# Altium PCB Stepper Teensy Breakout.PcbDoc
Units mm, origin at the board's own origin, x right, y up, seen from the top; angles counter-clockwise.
Board outline 195.58 x 105.66 mm, 2 copper layers (Top Layer, Bottom Layer); 65 components, 54 nets, 291 pads, 5 vias.
Unrouted connection lines stored in the file: 1.
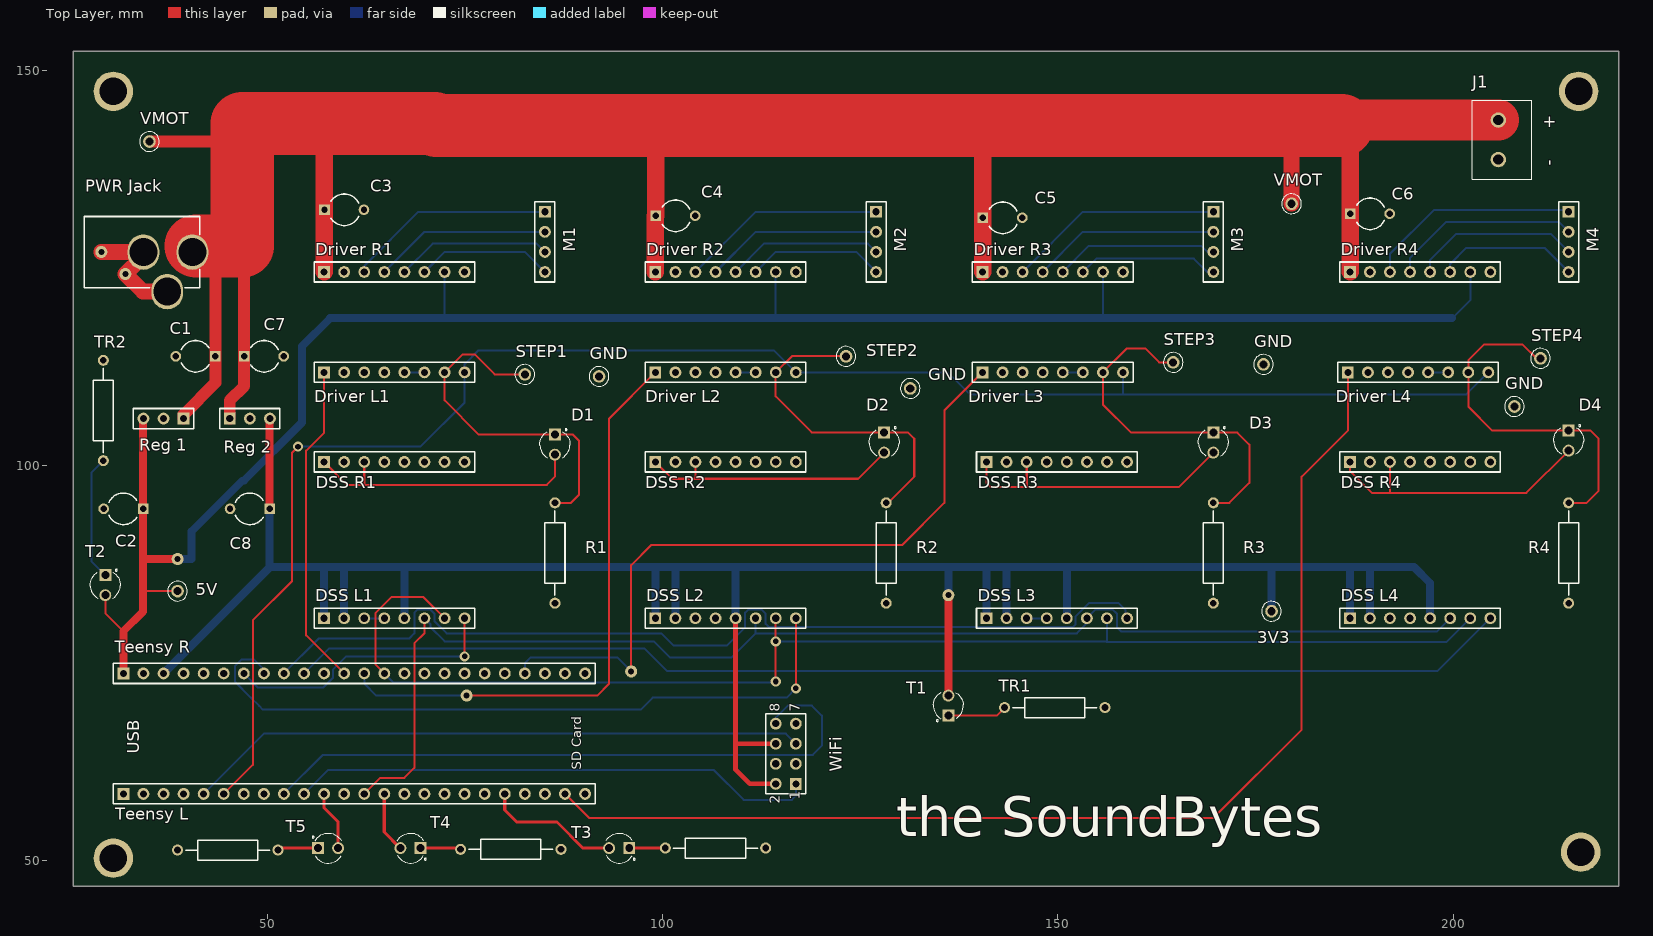
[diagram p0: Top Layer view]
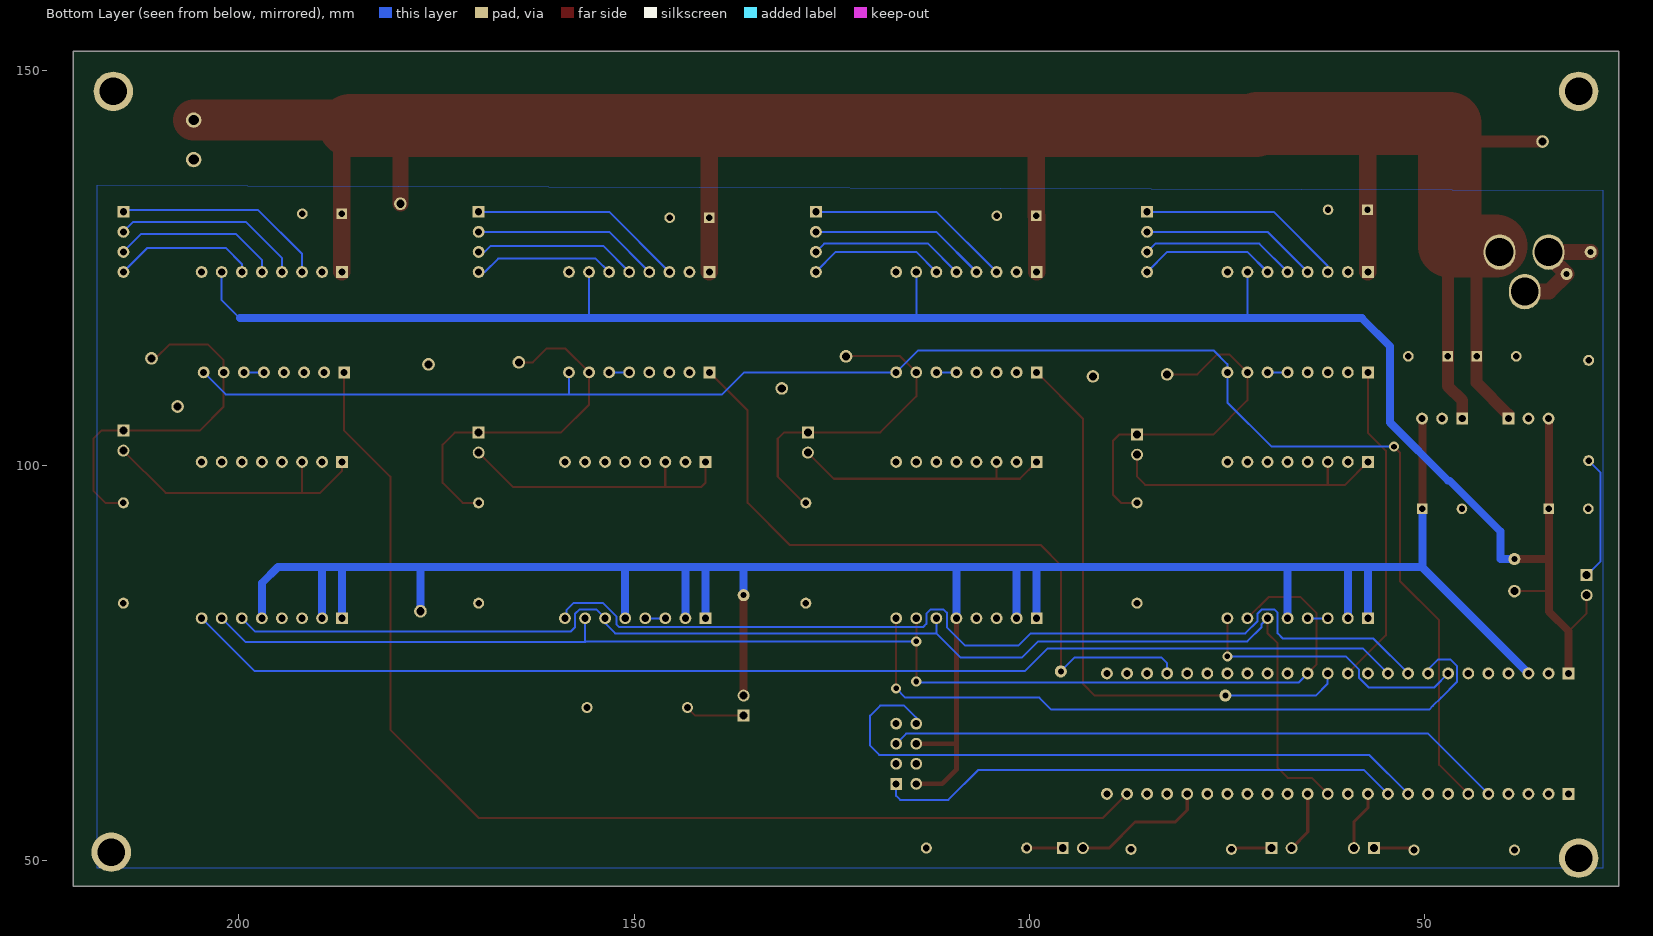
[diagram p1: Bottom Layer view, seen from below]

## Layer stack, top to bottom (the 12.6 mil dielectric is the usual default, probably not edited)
Top Solder: solder mask 0.0102, Solder Resist, Dk 3.5
Top Layer: signal copper 0.0356
Dielectric 1: dielectric 0.32, FR-4, Dk 4.8
Bottom Layer: signal copper 0.0356
Bottom Solder: solder mask 0.0102, Solder Resist, Dk 3.5

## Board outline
25.4,46.736 220.98,46.736 220.98,152.4 25.4,152.4

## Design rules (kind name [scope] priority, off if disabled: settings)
Clearance [All] p1: gap=0.254
PolygonConnect [All] p1: connectstyle=Relief reliefconductorwidth=0.254 reliefentries=4 polygonreliefangle="90 Angle" airgapwidth=0.254
RoutingVias [All] p1: holewidth=0.711 width=1.27 viastyle="Through Hole" minholewidth=0.711 minwidth=1.27 maxholewidth=0.711 maxwidth=1.27
SolderMaskExpansion [All] p1: expansion=0.102
Width Width_1 [All] p1: maxlimit=0.28 minlimit=0.28 preferedwidth=0.28 minimp=50.000000 maximp=50.000000 favimp=50.000000
Width [InNet('VMOT')] p2: maxlimit=8.2 minlimit=7.6 preferedwidth=8 minimp=50.000000 maximp=50.000000 favimp=50.000000
30 further rules are at their usual default settings.

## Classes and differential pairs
component class "Stepper Teensy Breakout": 3V3 5V C1 C2 C3 C4 C5 C6 C7 C8 D1 D2 D3 D4 "Driver L1" "Driver L2" "Driver L3" "Driver L4" "Driver R1" "Driver R2" "Driver R3" "Driver R4" "DSS L1" "DSS L2" "DSS L3" "DSS L4" "DSS R1" "DSS R2" "DSS R3" "DSS R4" GND J1 M1 M2 M3 M4 "PWR Jack" R1 R2 R3 R4 "Reg 1" "Reg 2" STEP1 STEP2 STEP3 STEP4 T1 T2 T3 T4 T5 "Teensy L" "Teensy R" TR1 TR2 VMOT WiFi ""

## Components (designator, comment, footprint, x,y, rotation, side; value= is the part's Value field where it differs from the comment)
3V3 "" TPCW51D250H460P 177.038,81.534 r0 top (schematic designator TP11)
5V "" TPCW51D250H460P 38.608,84.074 r90 top (schematic designator TP10)
C1 "Cap2" CAPR5-4X5 40.894,113.792 r180 top
C2 "Cap2" CAPR5-4X5 31.75,94.488 r180 top
C3 "" CAPR5-4X5 59.69,132.334 r0 top
C4 "Cap2" CAPR5-4X5 101.6,131.572 r0 top
C5 "Cap2" CAPR5-4X5 143.002,131.318 r0 top
C6 "Cap2" CAPR5-4X5 189.484,131.826 r0 top
C7 "Cap2" CAPR5-4X5 49.53,113.792 r0 top
C8 "Cap2" CAPR5-4X5 47.752,94.488 r180 top
D1 "LED2" LED_LTL-1CHYE_LTL-1CHYE(Primary) 86.36,102.616 r270 top
D2 "LED2" LED_LTL-1CHYE_LTL-1CHYE(Primary) 128.016,102.87 r270 top
D3 "LED2" LED_LTL-1CHYE_LTL-1CHYE(Primary) 169.672,102.87 r270 top
D4 "LED2" LED_LTL-1CHYE_LTL-1CHYE(Primary) 214.63,103.124 r270 top
"Driver L1" "Header 8" HDR1X8 57.15,111.76 r0 top locked
"Driver L2" "Header 8" HDR1X8 99.06,111.76 r0 top locked
"Driver L3" "Header 8" HDR1X8 140.462,111.76 r0 top locked
"Driver L4" "Header 8" HDR1X8 186.69,111.76 r0 top locked
"Driver R1" "Header 8" HDR1X8 57.15,124.46 r0 top locked
"Driver R2" "Header 8" HDR1X8 99.06,124.46 r0 top locked
"Driver R3" "Header 8" HDR1X8 140.462,124.46 r0 top locked
"Driver R4" "Header 8" HDR1X8 186.944,124.46 r0 top locked
"DSS L1" "Header 8" HDR1X8 57.15,80.645 r0 top locked
"DSS L2" "Header 8" HDR1X8 99.06,80.645 r0 top
"DSS L3" "Header 8" HDR1X8 140.97,80.645 r0 top locked
"DSS L4" "Header 8" HDR1X8 186.944,80.645 r0 top
"DSS R1" "Header 8" HDR1X8 57.15,100.42 r0 top locked
"DSS R2" "Header 8" HDR1X8 99.06,100.42 r0 top
"DSS R3" "Header 8" HDR1X8 140.97,100.42 r0 top
"DSS R4" "Header 8" HDR1X8 186.944,100.42 r0 top
GND "" TPCW51D250H460P 207.772,107.442 r0 top (schematic designator TP8)
GND "" TPCW51D250H460P 91.948,111.252 r0 top (schematic designator TP7)
GND "" TPCW51D250H460P 176.022,112.776 r0 top (schematic designator TP6)
GND "" TPCW51D250H460P 131.318,109.728 r0 top (schematic designator TP5)
J1 "" 691102710002 205.74,141.184 r270 top
M1 "Header 4" HDR1X4 85.09,132.08 r270 top (schematic designator "Motor 1")
M2 "Header 4" HDR1X4 127,132.08 r270 top (schematic designator "Motor 2")
M3 "Header 4" HDR1X4 169.672,132.08 r270 top (schematic designator "Motor 3")
M4 "Header 4" HDR1X4 214.63,132.08 r270 top (schematic designator "Motor 4")
"PWR Jack" "PWR2.5" KLD-0202 26.79,126.984 r0 top
R1 "Res Semi" AXIAL-0.5 86.36,88.9 r90 top
R2 "Res Semi" AXIAL-0.5 128.27,88.9 r90 top
R3 "Res Semi" AXIAL-0.5 169.672,88.9 r90 top
R4 "Res Semi" AXIAL-0.5 214.63,88.9 r90 top
"Reg 1" "Header 3" HDR1X3 39.37,105.918 r180 top (schematic designator "Sw Reg")
"Reg 2" "Header 2" HDR1X3 45.212,105.918 r0 top (schematic designator "Sw Reg1")
STEP1 "" TPCW51D250H460P 82.55,111.506 r0 top (schematic designator TP1)
STEP2 "" TPCW51D250H460P 123.19,113.792 r0 top (schematic designator TP2)
STEP3 "" TPCW51D250H460P 164.592,113.03 r0 top (schematic designator TP3)
STEP4 "" TPCW51D250H460P 211.074,113.538 r0 top (schematic designator TP4)
T1 "LTL-1CHYE" LED_LTL-1CHYE_LTL-1CHYE(Primary) 136.144,69.596 r90 top
T2 "LTL-1CHYE" LED_LTL-1CHYE_LTL-1CHYE(Primary) 29.464,84.836 r270 top
T3 "LTL-1CHYE" LED_LTL-1CHYE_LTL-1CHYE(Primary) 94.488,51.562 r180 top
T4 "LTL-1CHYE" LED_LTL-1CHYE_LTL-1CHYE(Primary) 68.072,51.562 r180 top
T5 "LTL-1CHYE" LED_LTL-1CHYE_LTL-1CHYE(Primary) 57.658,51.562 r0 top
"Teensy L" "Header 24" HDR1X24 31.75,58.42 r0 top locked
"Teensy R" "Header 24" HDR1X24 31.75,73.66 r0 top locked
TR1 "" AXIAL-0.5 149.606,69.342 r180 top
TR2 "" AXIAL-0.5 29.21,106.934 r270 top
TR3 "" AXIAL-0.5 106.68,51.562 r180 top
TR4 "" AXIAL-0.5 80.772,51.402 r180 top
TR5 "" AXIAL-0.5 44.958,51.308 r180 top
VMOT "" TPCW51D250H460P 179.578,133.096 r180 top (schematic designator TP12)
VMOT "" TPCW51D250H460P 35.052,140.97 r0 top (schematic designator TP9)
WiFi "Header 4X2" HDR2X4 116.84,59.69 r90 top (schematic designator ESP)

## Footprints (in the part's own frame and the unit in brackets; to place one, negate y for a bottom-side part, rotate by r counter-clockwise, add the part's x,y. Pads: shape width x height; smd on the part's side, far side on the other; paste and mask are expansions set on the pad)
691102710002 [mm]
  round 1.95 hole 1.3: 1(-2.5,0) 2(2.5,0)
  silkscreen extent -5,-3.3 5,4.2
AXIAL-0.5 [mm] "Axial Device, Thru-Hole; 2 Leads; 0.5 in Pin Spacing"
  round 1.4 hole 0.85: 1(-6.35,0) 2(6.35,0)
  silkscreen extent -5.33,-1.27 5.33,1.27
CAPR5-4X5 [mm] "Capacitor; 2 Leads"
  rect 1.35x1.35 hole 0.8: 1(-2.5,0)
  round 1.35 hole 0.8: 2(2.5,0)
  silkscreen extent -1.69,-2 1.82,2
HDR1X3 [mm] "Connector; Header; 3 Position"
  rect 1.5x1.5 hole 0.9: 1(0,0)
  round 1.5 hole 0.9: 2(2.54,0) 3(5.08,0)
  silkscreen extent -1.27,-1.27 6.35,1.27
HDR1X4 [mm] "Connector; Header; 4 Position"
  rect 1.5x1.5 hole 0.9: 1(0,0)
  round 1.5 hole 0.9: 2(2.54,0) 3(5.08,0) 4(7.62,0)
  silkscreen extent -1.27,-1.27 8.89,1.27
HDR1X8 [mm] "Connector; Header; 8 Position"
  rect 1.5x1.5 hole 0.9: 1(0,0)
  round 1.5 hole 0.9: 2(2.54,0) 3(5.08,0) 4(7.62,0) 5(10.16,0) 6(12.7,0) 7(15.24,0) 8(17.78,0)
  silkscreen extent -1.27,-1.27 19.05,1.27
HDR1X24 [mm] "Connector; Header; 24 Position"
  rect 1.5x1.5 hole 0.9: 1(0,0)
  round 1.5 hole 0.9: 2(2.54,0) 3(5.08,0) 4(7.62,0) 5(10.16,0) 6(12.7,0) 7(15.24,0) 8(17.78,0) 9(20.32,0) 10(22.86,0) 11(25.4,0) 12(27.94,0) 13(30.48,0) 14(33.02,0) 15(35.56,0) 16(38.1,0) 17(40.64,0) 18(43.18,0) 19(45.72,0) 20(48.26,0) 21(50.8,0) 22(53.34,0) 23(55.88,0) 24(58.42,0)
  silkscreen extent -1.27,-1.27 59.69,1.27
HDR2X4 [mm] "Connector; Header; 4x2 Position"
  rect 1.5x1.5 hole 0.9: 1(0,0)
  round 1.5 hole 0.9: 2(0,2.54) 3(2.54,0) 4(2.54,2.54) 5(5.08,0) 6(5.08,2.54) 7(7.62,0) 8(7.62,2.54)
  silkscreen extent -1.27,-1.27 8.89,3.81
KLD-0202 [mm] "DC Power Jack, 2.5mm, KLD Series, PCB Mount"
  oval 4x4.5 hole 3.5: 1(13.7,0) 2(7.5,0) 3(10.5,-5)
  round 1.5 hole 0.2: 1A(13.7,-1.25) 1B(13.7,1.25) 2A(7.5,-1) 2B(7.5,1) 3A(9.5,-5) 3B(11.5,-5)
  silkscreen extent 0,-4.5 14.6,4.5
LED_LTL-1CHYE_LTL-1CHYE(Primary) [mm]
  round 1.508 hole 1: A(1.27,0)
  rect 1.508x1.508 hole 1: C(-1.27,0)
  silkscreen extent -2.03,-1.9 1.66,1.9
TPCW51D250H460P [mm]
  round 1.6 hole 1.02: 1(0,0)
  silkscreen extent -1.25,-1.25 1.25,1.25

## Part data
3V3 5V GND GND GND GND STEP1 STEP2 STEP3 STEP4 VMOT VMOT: library part 5003, "Test Point; Orange; Thru-Hole; Snap-Fit; SilverPlate; 0.040 in. Dia.; 0.300 In."
C1 C2 C4 C5 C6 C7 C8: "Capacitor"
C3: library part Cap2, "Capacitor"
D1 D2 D3 D4: library part LTL-1CHYE, "Yellow 3.1 mm 45° Tinted Clear 40 mcd 2.1 V LED Through Hole"
"Driver L1" "Driver L2" "Driver L3" "Driver L4" "Driver R1" "Driver R2" "Driver R3" "Driver R4" "DSS L1" "DSS L2" "DSS L3" "DSS L4" "DSS R1" "DSS R2" "DSS R3" "DSS R4": "Header, 8-Pin"
J1: library part 691102710002, "102 Series 5mm Pitch Straight, PCB Terminal Block, Through Hole, 2 Way"
M1 M2 M3 M4: "Header, 4-Pin"
"PWR Jack": "Low Voltage Power Supply Connector"
R1 R2 R3 R4: "Semiconductor Resistor"
"Reg 1": "Header, 3-Pin"
"Reg 2": library part "Header 3", "Header, 3-Pin"
T1 T2 T3 T4 T5: "Yellow 3.1 mm 45° Tinted Clear 40 mcd 2.1 V LED Through Hole"
"Teensy L" "Teensy R": "Header, 24-Pin"
TR1 TR2 TR3 TR4 TR5: library part "Res Semi", "Semiconductor Resistor"
WiFi: "Header, 4-Pin, Dual row"

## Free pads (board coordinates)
  round 5 hole 3.5: 0(30.48,147.32) 6(215.9,147.32) 7(216.154,51.054) 8(30.48,50.292)
  round 1.524 hole 0.762: 2(28.956,127) 3(32.004,124.206) 5(38.608,88.138) 9(75.184,70.866) 10(96.012,73.914) 11(136.144,83.566)

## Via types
v1: diameter 1.27, hole 0.711, Top Layer to Bottom Layer, 5 vias

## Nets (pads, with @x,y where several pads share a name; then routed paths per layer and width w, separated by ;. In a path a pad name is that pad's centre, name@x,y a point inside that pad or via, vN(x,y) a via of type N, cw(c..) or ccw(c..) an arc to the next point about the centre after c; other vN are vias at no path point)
1A_A: "Driver R1.5" M1.3 | length 19.7
  Bottom Layer w0.254: 67.31,124.46 70.891,128.041 84.049,128.041 M1.3
1A_B: "Driver R2.5" M2.3 | length 19.7
  Bottom Layer w0.254: 109.22,124.46 112.801,128.041 125.959,128.041 M2.3
1A_C: "Driver R3.5" M3.3 | length 20.7
  Bottom Layer w0.254: 150.622,124.46 153.924,127.762 168.148,127.762 168.91,127 M3.3
1A_D: "Driver R4.5" M4.3 | length 21.4
  Bottom Layer w0.254: 197.104,124.46 197.104,125.984 200.406,129.286 212.344,129.286 M4.3
1B_A: "Driver R1.6" M1.4 | length 17.3
  Bottom Layer w0.254: 69.85,124.46 72.39,127 82.55,127 M1.4
1B_B: "Driver R2.6" M2.4 | length 17.3
  Bottom Layer w0.254: 111.76,124.46 114.3,127 124.46,127 M2.4
1B_C: "Driver R3.6" M3.4 | length 17.9
  Bottom Layer w0.254: 153.162,124.46 154.864,126.162 167.208,126.162 168.91,124.46 M3.4
1B_D: "Driver R4.6" M4.4 | length 18.1
  Bottom Layer w0.254: 199.644,124.46 199.644,125.476 201.676,127.508 211.582,127.508 M4.4
2A_A: "Driver R1.4" M1.2 | length 22.4
  Bottom Layer w0.254: 64.77,124.46 69.85,129.54 M1.2
2A_B: "Driver R2.4" M2.2 | length 22.4
  Bottom Layer w0.254: 106.68,124.46 111.76,129.54 M2.2
2A_C: "Driver R3.4" M3.2 | length 23.7
  Bottom Layer w0.254: 148.082,124.46 153.162,129.54 M3.2
2A_D: "Driver R4.4" M4.2 | length 24.3
  Bottom Layer w0.254: 194.564,124.46 194.564,126.238 199.136,130.81 213.36,130.81 M4.2
2B_A: "Driver R1.3" M1.1 | length 26.5
  Bottom Layer w0.254: 62.23,124.46 62.23,125.222 69.088,132.08 M1.1
2B_B: "Driver R2.3" M2.1 | length 26
  Bottom Layer w0.254: 104.14,124.46 111.76,132.08 M2.1
2B_C: "Driver R3.3" M3.1 | length 27.3
  Bottom Layer w0.254: 145.542,124.46 153.162,132.08 M3.1
2B_D: "Driver R4.3" M4.1 | length 27.3
  Bottom Layer w0.254: 192.024,124.46 192.024,126.746 197.612,132.334 214.376,132.334 M4.1
3V3: 3V3.1 "DSS L1.1" "DSS L1.2" "DSS L1.5" "DSS L2.1" "DSS L2.2" "DSS L2.5" "DSS L3.1" "DSS L3.2" "DSS L3.5" "DSS L4.1" "DSS L4.2" "DSS L4.5" "Reg 2.3" "Teensy R.3" C8.1 pad.11 T1.A WiFi.2 WiFi.6 | length 313.1
  Top Layer w0.6: 109.22,80.645 109.22,64.77 ; WiFi.2 110.998,59.69 109.22,61.468 109.22,64.77 ; WiFi.6 109.22,64.77
  Top Layer w1: C8.1 50.252,105.878 50.292,105.918 ; T1.A pad.11
  Bottom Layer w1: 36.83,73.66 50.252,87.082 50.252,87.122 ; C8.1 50.252,87.122 ; 57.15,80.645 57.15,87.122 ; 59.69,80.645 59.69,87.122 ; 67.31,80.645 67.31,87.122 ; 99.06,80.645 99.06,87.122 ; 101.6,80.645 101.6,87.122 ; 109.22,80.645 109.22,87.122 ; pad.11 136.144,87.122 ; 140.97,80.645 140.97,87.122 ; 143.51,80.645 143.51,87.122 ; 151.13,80.645 151.13,87.122 ; 3V3.1 177.038,87.122 ; 186.944,80.645 186.944,87.122 ; 189.484,80.645 189.484,87.122 ; 197.104,80.645 197.104,85.09 195.072,87.122 189.484,87.122 ; 50.252,87.122 57.15,87.122 ; 57.15,87.122 59.69,87.122 ; 59.69,87.122 67.31,87.122 ; 67.31,87.122 99.06,87.122 ; 99.06,87.122 101.6,87.122 ; 101.6,87.122 109.22,87.122 ; 109.22,87.122 136.144,87.122 ; 136.144,87.122 140.97,87.122 ; 140.97,87.122 143.51,87.122 ; 143.51,87.122 151.13,87.122 ; 151.13,87.122 177.038,87.122 ; 177.038,87.122 186.944,87.122 ; 186.944,87.122 189.484,87.122
5V: 5V.1 "Driver R1.7" "Driver R2.7" "Driver R3.7" "Driver R4.7" "Reg 1.3" "Teensy R.1" C2.1 pad.5 T2.A | length 253.5
  Top Layer w0.254: T2.A 29.464,81.28 31.75,78.994 ; 34.25,84.074 5V.1
  Top Layer w1: 31.75,73.66 31.75,78.994 34.25,81.494 34.25,84.074 34.25,88.138 ; 34.29,105.918 34.25,105.878 C2.1 34.25,88.138 ; pad.5 34.25,88.138
  Bottom Layer w0.254: 72.39,118.618 72.39,124.46 ; 114.3,118.618 114.3,124.46 ; 155.702,118.618 155.702,124.46 ; 199.898,118.618 202.184,120.904 202.184,124.46
  Bottom Layer w1: pad.5 40.393,88.138 40.393,91.65 46.787,98.044 46.99,98.044 54.356,105.41 54.356,115.062 57.912,118.618 72.39,118.618 114.3,118.618 155.702,118.618 199.898,118.618
24: "Teensy L.14" T4.A | length 7.7
  Top Layer w0.4: 64.77,58.42 64.77,53.594 T4.A
28: "Teensy L.20" T3.A | length 17.2
  Top Layer w0.4: 80.01,58.42 80.01,56.388 81.534,54.864 86.614,54.864 89.916,51.562 T3.A
CS1: "DSS L1.8" "Teensy R.7" | length 35.7
  Top Layer w0.254: v1(74.93,75.819) 74.93,80.645
  Bottom Layer w0.254: 46.99,73.66 48.768,71.882 57.023,71.882 58.293,73.152 58.293,74.168 59.944,75.819 v1(74.93,75.819)
CS2: "DSS L2.8" "Teensy R.8" | length 89.4
  Top Layer w0.254: v1(116.84,71.78) 116.84,80.645
  Bottom Layer w0.254: 49.53,73.66 49.53,74.168 48.26,75.438 46.736,75.438 45.847,74.549 45.847,72.644 47.879,70.612 48.938,69.553 49.403,69.088 97.199,69.088 98.723,70.612 115.672,70.612 v1(116.84,71.78)
CS3: "DSS L3.8" "Teensy R.9" | length 121.8
  Bottom Layer w0.254: 52.07,73.66 56.49,78.08 67.92,78.08 68.58,78.74 68.58,81.356 69,81.776 70.548,81.776 71.12,81.204 71.12,80.264 72.644,78.74 99.822,78.74 101.346,77.216 108.153,77.216 110.439,79.502 110.439,81.356 110.859,81.776 112.458,81.776 113.03,81.204 113.03,79.934 113.45,79.514 151.892,79.514 152.261,79.883 152.261,80.887 153.924,82.55 157.702,82.55 158.535,81.717 158.535,80.86 158.75,80.645
CS4: "DSS L4.8" "Teensy R.10" | length 155.4
  Bottom Layer w0.254: 54.61,73.66 57.785,76.835 97.663,76.835 100.559,73.939 198.018,73.939 204.724,80.645
DIR: "Driver L1.8" "Driver L2.8" "Driver L3.8" "Driver L4.8" "Teensy L.6" | length 212.6
  Top Layer w0.254: 44.45,58.42 48.133,62.103 48.133,80.391 53.086,85.344 53.086,101.6 v1(53.848,102.362)
  Bottom Layer w0.254: v1(53.848,102.362) 69.342,102.362 74.93,107.95 74.93,111.76 74.93,112.801 76.683,114.554 114.046,114.554 116.84,111.76 136.068,111.76 138.862,108.966 158.242,108.966 ; 158.242,111.76 158.242,108.966 ; 204.47,111.76 201.676,108.966 158.242,108.966
ENA1: "Driver L1.1" "Teensy R.12" | length 41
  Top Layer w0.254: 57.15,111.76 57.15,104.14 54.864,101.854 54.864,78.486 59.69,73.66
ENA2: "Driver L2.1" "Teensy R.13" pad.9 | length 75.3
  Top Layer w0.254: pad.9 91.694,70.866 93.218,72.39 93.218,105.918 99.06,111.76
  Bottom Layer w0.254: 62.23,73.66 62.23,72.39 63.754,70.866 pad.9
ENA3: "Driver L3.1" "Teensy R.21" pad.10 | length 90.6
  Top Layer w0.254: pad.10 96.012,87.376 98.552,89.916 130.302,89.916 135.636,95.25 135.636,106.934 140.462,111.76
  Bottom Layer w0.254: 82.55,73.66 82.55,74.93 83.312,75.692 94.234,75.692 pad.10
ENA4: "Driver L4.1" "Teensy L.23" | length 146.7
  Top Layer w0.254: 87.63,58.42 90.678,55.372 169.672,55.372 180.848,66.548 180.848,98.552 186.69,104.394 186.69,111.76
GND: "Driver R1.2" "Driver R1.8" "Driver R2.2" "Driver R2.8" "Driver R3.2" "Driver R3.8" "Driver R4.2" "Driver R4.8" "DSS L1.3" "DSS L1.4" "DSS L2.3" "DSS L2.4" "DSS L3.3" "DSS L3.4" "DSS L4.3" "DSS L4.4" "PWR Jack.2" "PWR Jack.2A" "PWR Jack.2B" "PWR Jack.3" "PWR Jack.3A" "PWR Jack.3B" "Reg 1.2" "Reg 2.2" "Teensy L.1" "Teensy R.2" "Teensy R.15" C1.2 C2.2 C3.2 C4.2 C5.2 C6.2 C7.2 C8.2 GND.1 J1.2 pad.2 pad.3 R1.1 R2.1 R3.1 R4.1 TR1.1 TR2.1 TR3.1 TR4.1 TR5.2 WiFi.7 | length 21
  Top Layer w2: pad.2 33.274,127 33.29,126.984 ; 34.29,125.984 34.036,126.238 ; 34.29,127.984 34.29,126.984 34.29,126.492 34.036,126.238 ; 37.29,121.984 36.29,121.984 34.226,121.984 pad.3 34.036,126.238
  Bottom Layer w0.254: 62.23,80.645 64.77,80.645 ; 146.05,80.645 148.59,80.645 ; 189.484,124.46 189.484,124.714
NetD1_A: "DSS R1.1" "DSS R1.3" D1.A | length 36.5
  Top Layer w0.254: 57.15,100.42 60.034,97.536 62.23,97.536 85.344,97.536 86.36,98.552 D1.A
  Top Layer w0.28: 62.23,97.536 62.23,100.42
NetD2_A: "DSS R2.1" "DSS R2.3" D2.A | length 33.3
  Top Layer w0.254: 99.06,100.42 101.182,98.298 104.14,98.298 124.714,98.298 D2.A
  Top Layer w0.28: 104.14,98.298 104.14,100.42
NetD3_A: "DSS R3.1" "DSS R3.3" D3.A | length 36.5
  Top Layer w0.254: 140.97,100.42 140.97,97.79 141.478,97.282 146.05,97.282 165.354,97.282 D3.A
  Top Layer w0.28: 146.05,97.282 146.05,100.42
NetD4_A: "DSS R4.1" "DSS R4.3" D4.A | length 36.1
  Top Layer w0.254: 186.944,100.42 186.944,99.314 189.738,96.52 192.024,96.52 209.296,96.52 D4.A
  Top Layer w0.28: 192.024,96.52 192.024,100.42
NetT1_C: T1.C TR1.2 | length 7.5
  Top Layer w0.254: T1.C 142.24,68.326 TR1.2
NetT2_C: T2.C TR2.2 | length 15.8
  Bottom Layer w0.254: TR2.2 27.686,99.06 27.686,87.884 T2.C
NetT3_C: T3.C TR3.2 | length 4.6
  Top Layer w0.4: T3.C TR3.2
NetT4_C: T4.C TR4.2 | length 5.1
  Top Layer w0.4: T4.C 74.262,51.562 TR4.2
NetT5_A: "Teensy L.11" T5.A | length 7.6
  Top Layer w0.4: 57.15,58.42 57.15,56.642 58.928,54.864 T5.A
NetT5_C: T5.C TR5.1 | length 5.2
  Top Layer w0.4: TR5.1 51.562,51.562 T5.C
PIN3: "Teensy L.5" WiFi.5 | length 78.6
  Bottom Layer w0.254: 41.91,58.42 49.53,66.04 115.57,66.04 WiFi.5
PIN7: "Teensy L.9" WiFi.8 | length 82.2
  Bottom Layer w0.254: 52.07,58.42 57.011,63.361 118.987,63.361 120.142,64.516 120.142,68.326 118.872,69.596 115.824,69.596 114.3,68.072 WiFi.8
PIN8: "Teensy L.10" WiFi.1 | length 66.8
  Bottom Layer w0.254: 54.61,58.42 57.658,61.468 106.426,61.468 110.236,57.658 116.332,57.658 116.84,58.166 WiFi.1
RESET1: "Driver L1.5" "Driver L1.6" | length 2.5
  Bottom Layer w0.254: 67.31,111.76 69.85,111.76
RESET2: "Driver L2.5" "Driver L2.6" | length 2.5
  Bottom Layer w0.254: 109.22,111.76 111.76,111.76
RESET3: "Driver L3.5" "Driver L3.6" | length 2.5
  Bottom Layer w0.254: 150.622,111.76 153.162,111.76
RESET4: "Driver L4.5" "Driver L4.6" | length 2.5
  Bottom Layer w0.254: 196.85,111.76 199.39,111.76
SCK: "DSS L1.7" "DSS L2.7" "DSS L3.7" "DSS L4.7" "Teensy R.14" | length 169.2
  Top Layer w0.254: 64.77,73.66 63.627,74.803 63.627,81.28 65.659,83.312 69.723,83.312 72.39,80.645 ; v1(114.3,72.644) v1(114.3,77.724) 114.3,80.645
  Bottom Layer w0.254: 64.77,73.66 65.913,72.517 v1@114.173,72.517 ; v1@114.046,72.39 v1@114.173,72.517 ; v1(114.3,72.644) v1@114.173,72.517 ; v1(114.3,77.724) 156.108,77.724 156.21,77.622 ; 156.21,80.645 156.21,77.622 ; 202.184,80.645 199.161,77.622 156.21,77.622
SDA: "DSS L1.6" "DSS L2.6" "DSS L3.6" "DSS L4.6" "Teensy L.13" | length 166.9
  Top Layer w0.254: 62.23,58.42 64.262,60.452 67.31,60.452 68.58,61.722 68.58,77.47 69.85,78.74 69.85,80.645
  Bottom Layer w0.254: 69.85,80.645 70.612,79.883 70.612,79.502 72.39,77.724 98.869,77.724 100.901,75.692 108.712,75.692 111.76,78.74 ; 111.76,80.645 111.76,78.74 ; 199.644,80.645 197.993,78.994 157.988,78.994 157.48,79.502 157.48,81.204 156.908,81.776 154.801,81.776 153.67,80.645 153.67,80.01 152.4,78.74 111.76,78.74
STEP1: "Driver L1.7" D1.C R1.2 STEP1.1 | length 45.2
  Top Layer w0.254: STEP1.1 78.74,111.506 76.2,114.046 74.676,114.046 72.39,111.76 72.39,108.204 76.708,103.886 D1.C 88.646,103.886 89.408,103.124 89.408,96.266 88.392,95.25 R1.2
STEP2: "Driver L2.7" D2.C R2.2 STEP2.1 | length 42.1
  Top Layer w0.254: STEP2.1@122.682,113.817 116.357,113.817 114.3,111.76 114.3,108.712 118.832,104.18 131.024,104.18 131.826,103.378 131.826,98.552 128.524,95.25 R2.2
  Bottom Layer w0.254: R2.2@128.016,95.504 R2.2
STEP3: "Driver L3.7" D3.C R3.2 STEP3.1 | length 46
  Top Layer w0.254: STEP3.1 162.814,113.03 161.036,114.808 158.75,114.808 155.702,111.76 155.702,107.696 159.258,104.14 D3.C 172.72,104.14 174.244,102.616 174.244,97.79 171.704,95.25 R3.2
STEP4: "Driver L4.7" D4.C R4.2 STEP4.1 | length 45.8
  Top Layer w0.254: STEP4.1 210.566,113.538 208.788,115.316 203.962,115.316 201.93,113.284 201.93,111.76 201.93,107.442 204.978,104.394 D4.C 217.424,104.394 218.44,103.378 218.44,96.774 216.916,95.25 R4.2
VMOT: "Driver R1.1" "Driver R2.1" "Driver R3.1" "Driver R4.1" "PWR Jack.1" "PWR Jack.1A" "PWR Jack.1B" "Reg 1.1" "Reg 2.1" C1.1 C3.1 C4.1 C5.1 C6.1 C7.1 J1.1 VMOT.1 | length 325.6
  Top Layer w0.254: 40.49,128.234 40.962,127.762 ; 57.15,124.46 57.19,124.5 ; 57.19,143.054 57.404,143.268 ; 71.108,143.268 71.374,143.002 ; C4.1@99.06,131.532 C4.1 ; 99.06,143.002 99.1,142.962 ; 140.462,124.46 140.502,124.5 ; 140.462,143.002 140.502,142.962 ; 185.928,143.002 186.984,141.946 ; 186.944,124.46 186.984,124.5
  Top Layer w0.28: 185.928,143.002 186.61,143.684
  Top Layer w1.5: VMOT.1@35.052,140.97 46.736,140.97 ; 39.37,105.918 39.37,106.426 43.394,110.45 C1.1 43.394,124.363 46.793,127.762 ; 45.212,105.918 45.212,108.204 47.03,110.022 C7.1 47.03,127.525
  Top Layer w2: VMOT.1@179.578,133.096 179.578,143.002
  Top Layer w2.2: 46.793,127.762 47.03,127.525 ; 57.19,124.5 C3.1 57.19,143.054 ; 99.06,124.46 C4.1@99.06,131.532 ; C4.1 99.1,142.962 ; 140.502,124.5 C5.1 140.502,142.962 ; 186.984,124.5 C6.1 186.984,141.946
  Top Layer w5.2: 186.61,143.684 J1.1
  Top Layer w8: 40.962,127.762 46.793,127.762 46.793,143.268 57.404,143.268 71.108,143.268 ; 71.374,143.002 99.06,143.002 140.462,143.002 179.578,143.002 185.928,143.002
pads on no net: "Driver L1.2" "Driver L1.3" "Driver L1.4" "Driver L2.2" "Driver L2.3" "Driver L2.4" "Driver L3.2" "Driver L3.3" "Driver L3.4" "Driver L4.2" "Driver L4.3" "Driver L4.4" "DSS R1.2" "DSS R1.4" "DSS R1.5" "DSS R1.6" "DSS R1.7" "DSS R1.8" "DSS R2.2" "DSS R2.4" "DSS R2.5" "DSS R2.6" "DSS R2.7" "DSS R2.8" "DSS R3.2" "DSS R3.4" "DSS R3.5" "DSS R3.6" "DSS R3.7" "DSS R3.8" "DSS R4.2" "DSS R4.4" "DSS R4.5" "DSS R4.6" "DSS R4.7" "DSS R4.8" "Teensy L.2" "Teensy L.3" "Teensy L.4" "Teensy L.7" "Teensy L.8" "Teensy L.12" "Teensy L.15" "Teensy L.16" "Teensy L.17" "Teensy L.18" "Teensy L.19" "Teensy L.21" "Teensy L.22" "Teensy L.24" "Teensy R.4" "Teensy R.5" "Teensy R.6" "Teensy R.11" "Teensy R.16" "Teensy R.17" "Teensy R.18" "Teensy R.19" "Teensy R.20" "Teensy R.22" "Teensy R.23" "Teensy R.24" WiFi.3 WiFi.4

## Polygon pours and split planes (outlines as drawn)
GND on Bottom Layer "GND" (hatched 90Degree grid 0.508 track 0.203, shelved, pour order 0): 27.432,134.784 27.432,49.022 217.932,49.022 217.932,135.441

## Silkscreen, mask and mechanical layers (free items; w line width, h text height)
Top Overlay:
  text "+" at 211.328,142.748 h1.52
  text "-" at 212.852,137.922 h1.52 r90
  text "USB" at 33.782,63.5 h1.52 r90
  text "SD Card" at 89.662,61.468 h1.2 r90
  text "the SoundBytes" at 129.54,53.086 h5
